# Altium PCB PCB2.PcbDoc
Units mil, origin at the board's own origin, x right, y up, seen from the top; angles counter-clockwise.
Board outline 4495.6 x 2805.51 mil, 2 copper layers (Top Layer, Bottom Layer), stack 61.756 mil thick; 146 components, 111 nets, 456 pads, 126 vias.
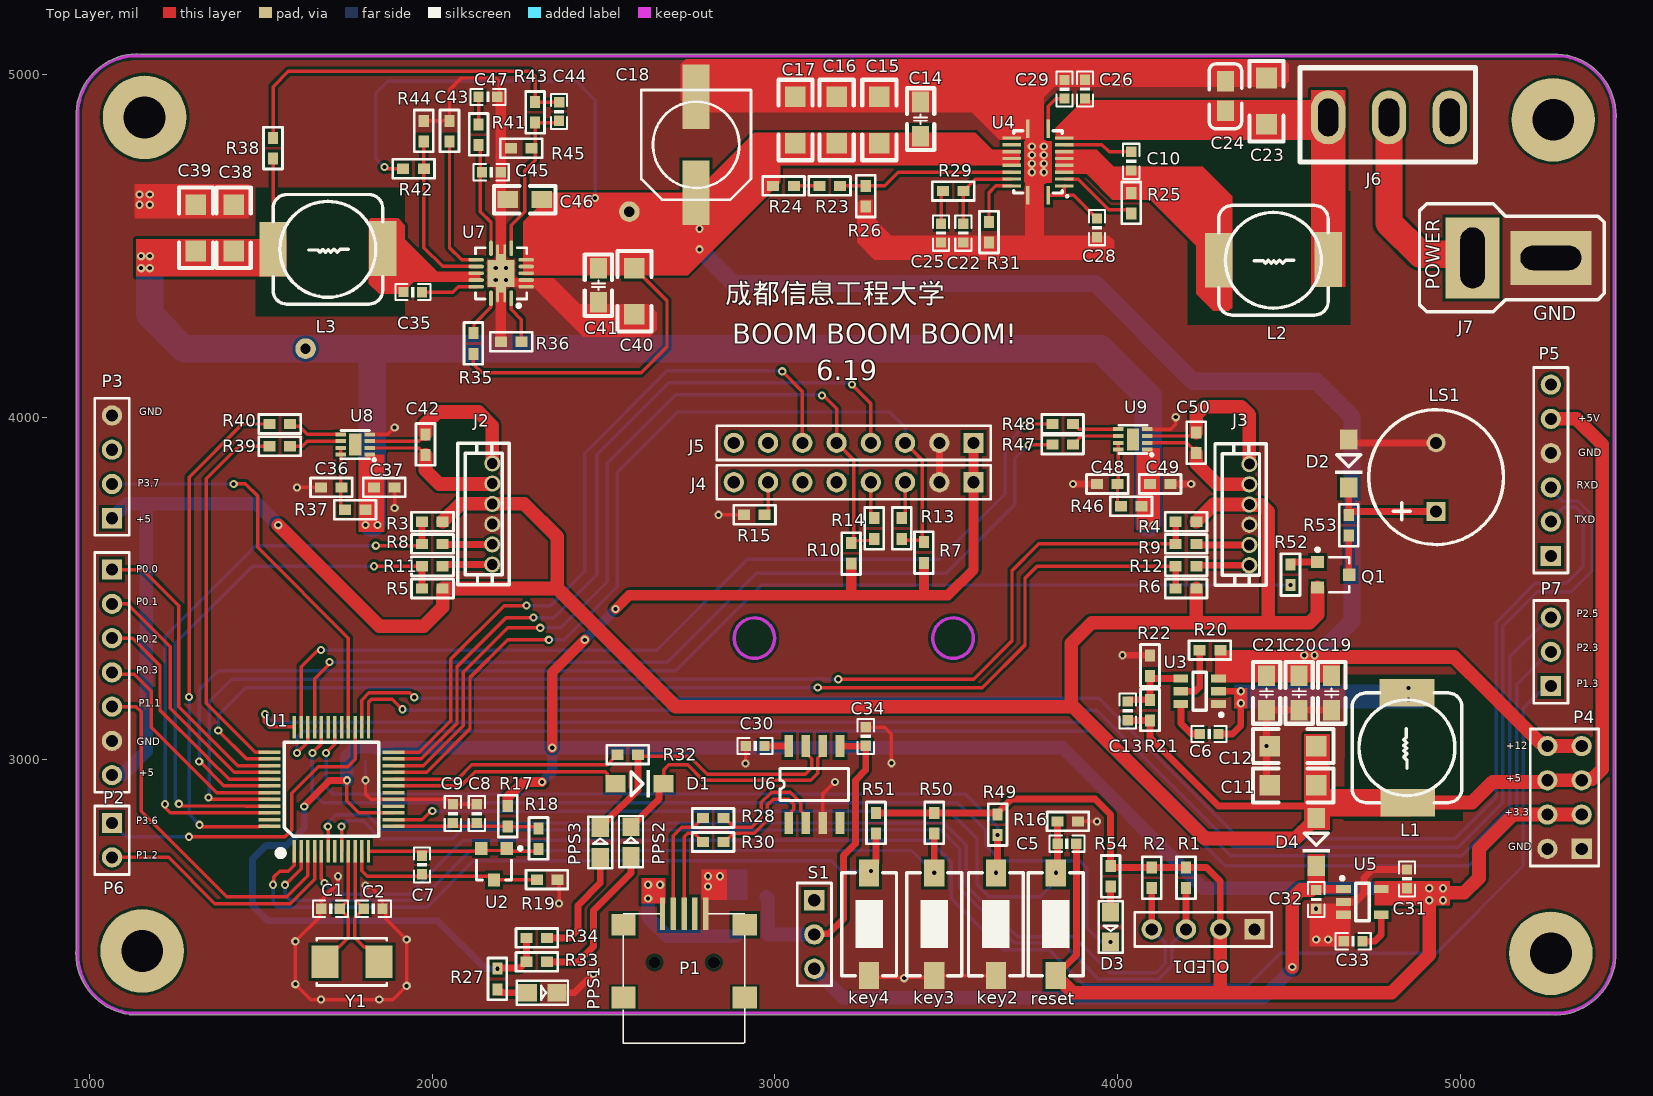
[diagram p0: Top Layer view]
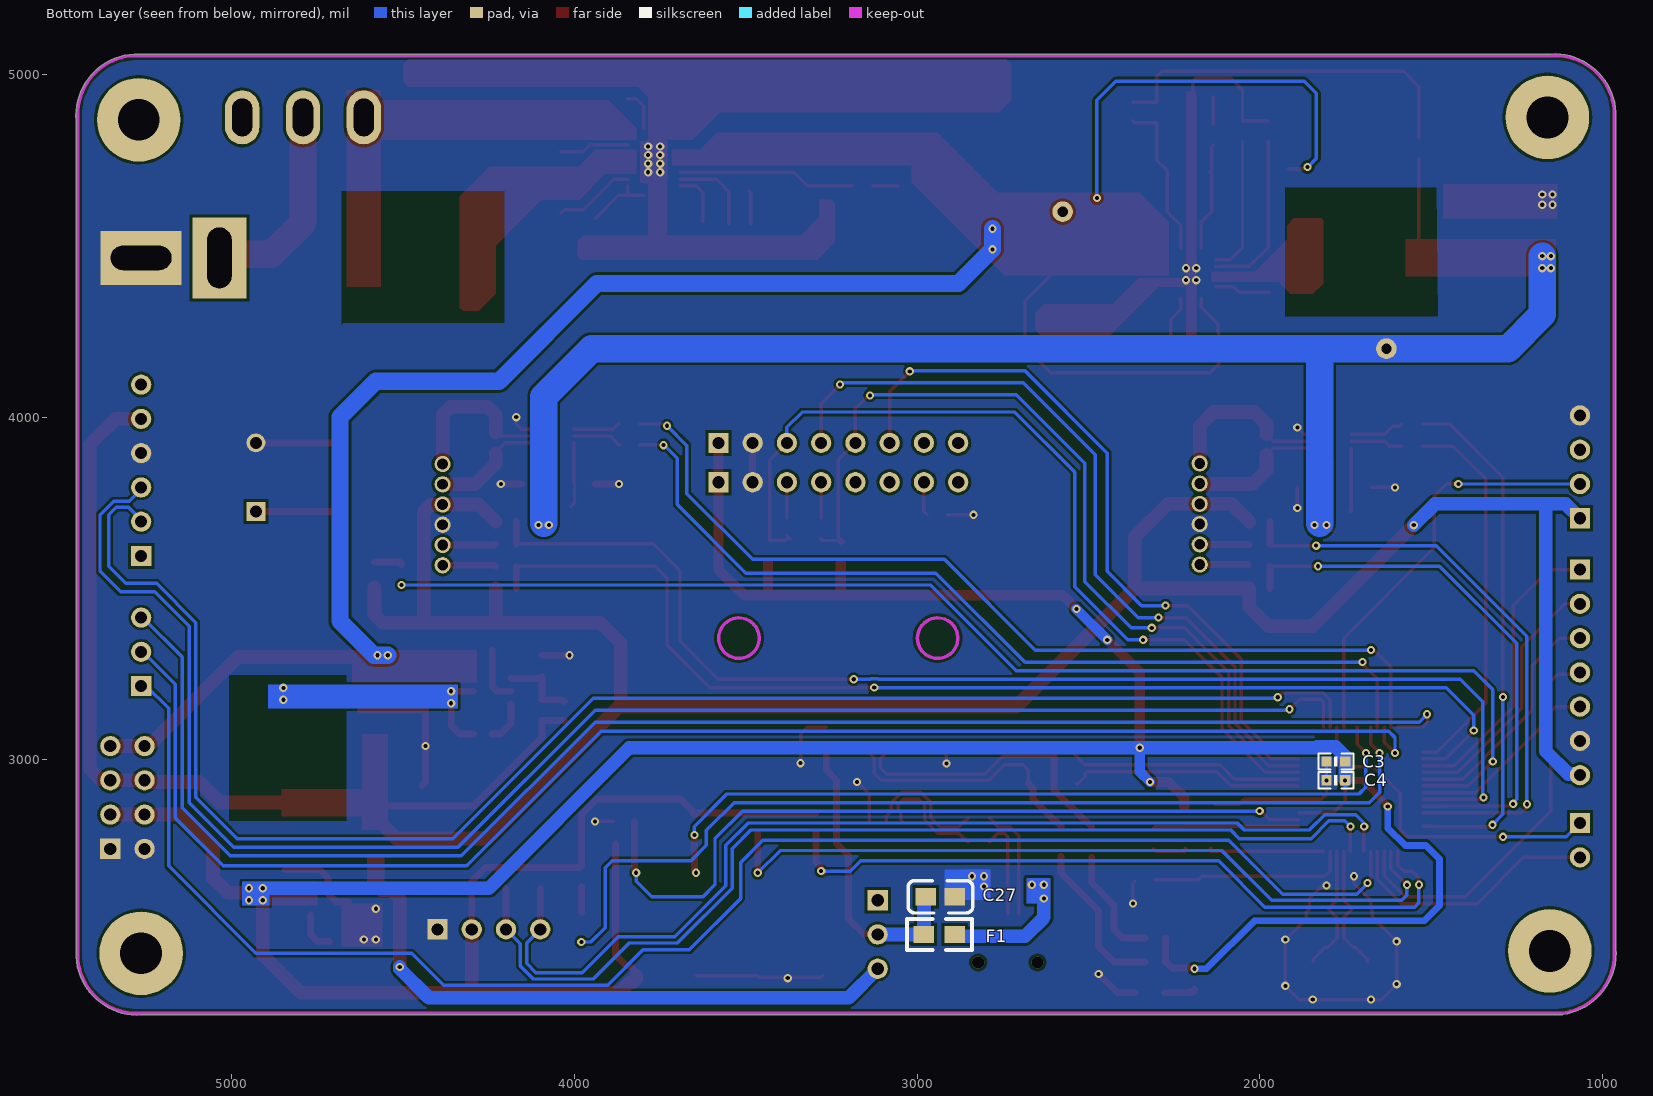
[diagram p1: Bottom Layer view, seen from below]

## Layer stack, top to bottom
Top Solder: solder mask 1, SM-001, Dk 4
Top Layer: signal copper 1.378
Dielectric 1: core 59, Core-043, Dk 4.3
Bottom Layer: signal copper 1.378
Bottom Solder: solder mask 1, SM-001, Dk 4

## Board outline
960.53,2417.73 cw(c965,2420) 959.98,2420 959.98,2424.87 cw(c1140,2435) 959.98,2445.13 959.98,4890 cw(c965,4890) 960,4890.38 cw(c1140,4880) 1150.14,5060.02 5282.5,5060.02 cw(c5282.5,5055) 5283.75,5059.86 cw(c5285,5055) 5285.29,5060.01 cw(c5275,4880) 5455.3,4880 cw(c5275,4880) 5455.02,4869.86 5455.02,2425 cw(c5450,2425) 5455.01,2424.68 ccw(c5275,2435) 5455.01,2424.71 5455.01,2424.68 cw(c5275,2435) 5264.86,2254.99 1130,2254.98 cw(c1130,2260) 1129.66,2255 ccw(c1140,2435) 1129.71,2254.99 1129.66,2255 cw(c1140,2435)

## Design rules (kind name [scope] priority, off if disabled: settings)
Clearance [All] p1: gap=8 ignorepadtopadclearanceinfootprint=FALSE
PolygonConnect [All] p1: connectstyle=Direct reliefconductorwidth=10 reliefentries=4 polygonreliefangle="90 Angle" airgapwidth=10
RoutingVias [All] p1: holewidth=28 width=50 viastyle="Through Hole" minholewidth=28 minwidth=50 maxholewidth=28 maxwidth=50
SolderMaskExpansion [All] p1: expansion=4 istentingtop=FALSE
Width [All] p1: maxlimit=100 minlimit=10 preferedwidth=10 minimp=50.000000 maximp=50.000000 favimp=50.000000
30 further rules are at their usual default settings.

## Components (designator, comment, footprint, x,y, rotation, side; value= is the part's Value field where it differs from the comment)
C1 "22PF" 0603-C 1730,2565 r180 top
C2 "22PF" 0603-C 1800,2565 r0 top
C3 "" 0603-C 1805,2940 r180 bottom value=10UF
C4 "" 0603-C 1805,2995 r180 bottom value=104
C5 "104" 0603-C 3825.5,2755.06 r0 top
C6 "" 0603-c 4295,3075 r180 top value=0.1UF
C7 "100nf" 0603-C 1970,2720 r270 top
C8 "10UF" 0603-C 2129.94,2815.5 r90 top
C9 "100NF" 0603-C 2059.94,2815.5 r90 top
C10 "" 0603-c 4040.06,4774.5 r270 top value=0.1uf
C11 "" 1206 4445,2925 r0 top value=22UF
C12 "" 1206 4445,3040 r0 top value=22UF
C13 "" 0603-c 4030,3170 r270 top value=6.8UF
C14 "" 0805C 3425,4920 r270 top value=1UF
C15 "" 1206 3305,4935 r270 top value=22UF
C16 "" 1206 3180,4935 r270 top value=22UF
C17 "" 1206 3060,4935 r270 top value=22UF
C18 "" CC88 2770,4795 r90 top value=220uf电解
C19 "" 0805c 4625,3245 r270 top value=10UF
C20 "" 0805c 4530,3245 r270 top value=10UF
C21 "" 0805c 4435,3245 r270 top value=0.1UF
C22 "" 0603-C 3550.06,4564.5 r270 top value=100PF
C23 "" 1206 4435,4855 r90 top value=47uf坦
C24 "" 0805-c 4315,4980 r270 top value=10uf
C25 "" 0603-C 3485.06,4564.5 r270 top value=6.8UF
C26 "" 0603-c 3905,4985 r270 top value=0.1uf
C27 "坦47uf" 0805-C 2975,2600 r180 bottom
C28 "" 0603-c 3939.94,4525.5 r90 top value=2.2uf
C29 "" 0603-C 3845,4930 r90 top value=47nf
C30 "0.1uf" 0603-C 2969.5,3039.94 r180 top
C31 "" 0603-C 4845.06,2679.5 r270 top value=1uf
C32 "" 0603-C 4580,2565 r90 top value=1uf
C33 "" 0603-C 4660.5,2470.06 r0 top value=0.1uf
C34 "0.1uf" 0603-C 3265,3095 r270 top
C35 "" 0603-c 1915.5,4365.06 r0 top value=0.1uf
C36 "0.1UF" 0603-r 1735,3795 r180 top
C37 "0.1UF" 0603-r 1830,3795 r0 top
C38 "" 1206 1420,4620 r270 top value=47uf
C39 "" 1206 1310,4620 r270 top value=47uf
C40 "" 1206 2590,4435 r270 top value=22uf坦
C41 "" 0805c 2485,4335 r90 top value=4.7uf
C42 "104" 0603-r 1980,3950 r270 top
C43 "" 0603-r 2050,4865 r270 top value=0.022uf
C44 "" 0603-c 2370,4865 r90 top value=470pf
C45 "" 0603-c 2199.5,4714.94 r180 top value=39pf
C46 "" 0805r 2220,4635 r0 top value=4.7uf
C47 "" 0603-c 2189.5,4934.94 r180 top value=3900pf
C48 "0.1UF" 0603-r 4000,3805 r180 top
C49 "0.1UF" 0603-r 4095,3805 r0 top
C50 "104" 0603-r 4230,3955 r270 top
D1 "二极管" DIODE_SOP 2535,2930 r0 top
D2 "DIODE" "DIODE_SOP - duplicate1" 4675,3935 r270 top
D3 "LED0" 0805-LED 3980,2507.36 r270 top
D4 "DIODE" "DIODE_SOP - duplicate1" 4580,2830 r270 top
F1 "500mA保险丝" "0805 - duplicate" 2890,2490 r0 bottom
J2 "CON6" XH6-1.5x1.5 2175,3865 r270 top
J3 "CON6" XH6-1.5x1.5 4385,3863.1 r270 top
J4 "CON8" HDR1X8 3580,3810 r180 top
J5 "CON8" HDR1X8 3580,3925 r180 top
J6 "主开关" 拨动开关 4790,4880 r90 top
J7 "T插" T型头 5138,4473 r0 top
key2 "KEY" KEY 3645,2520 r270 top
key3 "KEY" KEY 3465,2520 r270 top
key4 "KEY" KEY 3275,2520 r270 top
L1 "Inductor" L8*8 4845,2875 r90 top value=4.7uh
L2 "PIMB   0630" L8*8 4615,4458 r180 top value=2.2uh
L3 "Inductor" L8*8 1855,4490 r180 top value=3.3uh
LS1 "SPEAK" BELL-5 4930,3725 r90 top
OLED1 "CON4" HDR1X4 4400,2505 r180 top
P1 "USB_Micro" "USB_MINI - duplicate" 2735,2172.05 r90 top
P2 "Header 7" HDR1X7 1065,3555 r270 top
P3 "Header 4" HDR1X4 1065,3705 r90 top
P4 "Header 4X2" HDR2X4 5355,2740 r90 top
P5 "Header 6" HDR1X6 5265,3595 r90 top
P6 "Header 2H" HDR1X2 1065,2815 r270 top
P7 "Header 3" HDR1X3 5265,3215 r90 top
PPS1 "LED" 0805-LED 2325,2320 r0 top
PPS2 "LED" 0805-LED 2580,2765 r90 top
PPS3 "LED" 0805-LED 2490,2762.64 r90 top
Q1 "PNP" SOT-23R 4625,3540 r270 top
R1 "" 0603-R 4200,2685 r270 top value=4.7K
R2 "" 0603-R 4100,2685 r270 top value=4.7K
R3 "10K" 0603-R 2030,3695 r180 top
R4 "10K" 0603-R 4230,3695 r180 top
R5 "10K" 0603-R 2030,3500 r180 top
R6 "10K" 0603-R 4230,3500 r180 top
R7 "" 0603-R 3435,3575 r90 top value=4.7K
R8 "510R" 0603-R 2030,3630 r180 top
R9 "510R" 0603-R 4230,3630 r180 top
R10 "" 0603-R 3222.5,3572.5 r90 top value=4.7K
R11 "510R" 0603-R 2030,3565 r180 top
R12 "510R" 0603-R 4230,3565 r180 top
R13 "200R" 0603-R 3370,3705 r270 top
R14 "200R" 0603-R 3290,3705 r270 top
R15 "4.7k" 0603-R 2970,3715 r180 top
R16 "10k" 0603-R 3885,2820 r180 top
R17 "Res1" 0603-R 2220,2865 r270 top value=0R
R18 "Res1" 0603-R 2310,2800 r270 top value=511R
R19 "Res1" 0603-R 2305,2650 r0 top value=0R
R20 "" 0603-r 4240,3320 r0 top value=10K
R21 "" 0603-r 4095,3175 r270 top value=54.9K
R22 "" 0603-r 4095,3305 r270 top value=10K
R23 "Res1" 0603-R 3130,4675 r0 top value=504K
R24 "Res1" 0603-R 3055,4675 r180 top value=100Ω微
R25 "" 0603-r 4040,4655 r270 top value=255k
R26 "Res1" 0603-R 3265,4675 r270 top value=56K
R27 "1K" 0603-R 2190,2390 r270 top
R28 "22R" 0603-R 2790,2830 r0 top
R29 "" 0603-R 3550,4660 r180 top value=121k
R30 "22R" 0603-R 2790,2760 r0 top
R31 "Res1" 0603-R 3625,4570 r270 top value=100K
R32 "300R" 0603-R 2600,3015 r180 top
R33 "1K" 0603-R 2335,2410 r180 top
R34 "1K" 0603-R 2335,2480 r180 top
R35 "" 0603-r 2120,4245 r270 top value=49.9K
R36 "" 0603-r 2260,4220 r180 top value=100K
R37 "1K" 0603-r 1745,3730 r0 top
R38 "" 0603-r 1535,4815 r270 top value=0R
R39 "200Ω" 0603-r 1525,3915 r0 top
R40 "200Ω" 0603-r 1525,3980 r0 top
R41 "Res1" 0603-r 2135,4855 r270 top value=4.64K
R42 "" 0603-r 1975,4725 r180 top value=35.7K
R43 "" 0603-r 2300,4860 r90 top value=19.89K
R44 "" 0603-r 1975,4865 r270 top value=8.06K
R45 "" 0603-r 2230,4785 r0 top value=2.21K
R46 "1K" 0603-r 4010,3740 r0 top
R47 "200Ω" 0603-r 3810,3920 r0 top
R48 "200Ω" 0603-r 3810,3980 r0 top
R49 "10K" 0603-R 3650,2840 r270 top
R50 "10k" 0603-R 3465,2845 r270 top
R51 "10k" 0603-R 3295,2845 r270 top
R52 "1k" 0603-R 4505,3570 r270 top value=1K
R53 "100R" 0603-R 4675,3655 r90 top
R54 "Res1" 0603-R 3980,2630 r90 top value=1K
reset "KEY" KEY 3820,2520 r270 top (schematic designator key1)
S1 "switch" HDR1X3 3115,2590 r270 top
U1 "STC8A8K64S4A12-48" LQFP48S 1597.5,2732.37 r90 top
U2 "TL431" SOT-23 2180,2700 r180 top
U3 "TPS562201" LC-SOT-23-6 4240,3200 r0 top
U4 "TPS61008" TPS61088改 3768,4744.92 r90 top
U5 "TPS79133" LC-SOT-23-5 4715,2585 r180 top
U6 "CH340N" SOP-8 3040,2815.59 r90 top
U7 "TPS54821" VQFN-14改 2200.83,4420 r90 top
U8 "drv8837" wson-8-2X2改 1775,3920 r180 top
U9 "drv8837" wson-8-2X2改 4045,3935 r180 top
Y1 "XTAL_5032" XTAL_5032 1765,2410 r180 top value=4M~33M

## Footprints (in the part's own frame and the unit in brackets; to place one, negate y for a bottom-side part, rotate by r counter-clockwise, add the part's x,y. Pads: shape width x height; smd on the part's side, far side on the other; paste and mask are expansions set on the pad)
0603-C [mil]
  rect 30x30 smd: 1(0,0) 2(54.5,-0.06)
  silkscreen extent -24,-24 79,24
0603-c [mil]
  rect 30x30 smd: 1(0,0) 2(54.5,-0.06)
  silkscreen extent -24,-24 79,24
0603-r [mil]
  rect 35x30 smd: 1(0,0) 2(60,0)
  silkscreen extent -31,-28 91,28, body extent -22,-19 82,19, height 39
0603-R [mil]
  rect 35x30 smd: 1(0,0) 2(60,0)
  silkscreen extent -31,-28 91,28, body extent -22,-19 82,19, height 39
"0805 - duplicate" [mil]
  rect 60x50 smd: 1(0,0) 2(90,0)
  silkscreen extent -50,-45 140,45
0805-c [mil]
  rect 60x50 smd: 1(0,0) 2(85,0)
  silkscreen extent -51,-47 138,47, body extent 3,-25 82,25, height 30
0805-C [mil]
  rect 60x50 smd: 1(0,0) 2(85,0)
  silkscreen extent -51,-47 138,47, body extent 3,-25 82,25, height 30
0805-LED [mm]
  rect 1.4x1.27 smd: 1(-1.21,0) 2(1,0)
  silkscreen extent -2.01,-0.89 1.8,0.89
0805C [mil]
  rect 60x49.21 smd: 1(0,0) 2(100,0)
  silkscreen extent -40,-40 140,40
0805c [mil]
  rect 60x49.21 smd: 1(0,0) 2(100,0)
  silkscreen extent -40,-40 140,40
0805r [mil]
  rect 60x49.21 smd: 1(0,0) 2(100,0)
  silkscreen extent -40,-40 140,40
1206 [mil]
  rect 60x60 smd: 1(0,0) 2(135,0)
  silkscreen extent -50,-50 185,50
BELL-5 [mil] "PIN:5MM,SIZE:10MM"
  rect 55x55 hole 35: 1(0,0)
  round 55 hole 35: 2(200,0)
  silkscreen extent -97,-197 297,197
CC88 [mm] "SMD;W:8mm;L:8mm;"
  rect 4.8x2 smd: 1(-3.556,0) 2(3.556,0)
  silkscreen extent -4.06,-4.06 4.06,4.06
DIODE_SOP [mm]
  rect 1.5x1.3 smd: 1(0,0) 2(3.556,0)
  silkscreen extent 1.14,-1.02 2.56,1.02
"DIODE_SOP - duplicate1" [mm]
  rect 1.5x1.3 smd: 1(0,0) 2(3.556,0)
  silkscreen extent 1.14,-1.02 2.56,1.02
HDR1X2 [mm] "Connector; Header; 2 Position"
  rect 1.5x1.5 hole 0.9: 1(0,0)
  round 1.5 hole 0.9: 2(2.54,0)
  silkscreen extent -1.27,-1.27 3.81,1.27
HDR1X3 [mm] "Connector; Header; 3 Position"
  rect 1.5x1.5 hole 0.9: 1(0,0)
  round 1.5 hole 0.9: 2(2.54,0) 3(5.08,0)
  silkscreen extent -1.27,-1.27 6.35,1.27
HDR1X4 [mm] "Connector; Header; 4 Position"
  rect 1.5x1.5 hole 0.9: 1(0,0)
  round 1.5 hole 0.9: 2(2.54,0) 3(5.08,0) 4(7.62,0)
  silkscreen extent -1.27,-1.27 8.89,1.27
HDR1X6 [mm] "Connector; Header; 6 Position"
  rect 1.5x1.5 hole 0.9: 1(0,0)
  round 1.5 hole 0.9: 2(2.54,0) 3(5.08,0) 4(7.62,0) 5(10.16,0) 6(12.7,0)
  silkscreen extent -1.27,-1.27 13.97,1.27
HDR1X7 [mm] "Connector; Header; 7 Position"
  rect 1.5x1.5 hole 0.9: 1(0,0)
  round 1.5 hole 0.9: 2(2.54,0) 3(5.08,0) 4(7.62,0) 5(10.16,0) 6(12.7,0) 7(15.24,0)
  silkscreen extent -1.27,-1.27 16.51,1.27
HDR1X8 [mm] "Connector; Header; 8 Position"
  rect 1.5x1.5 hole 0.9: 1(0,0)
  round 1.5 hole 0.9: 2(2.54,0) 3(5.08,0) 4(7.62,0) 5(10.16,0) 6(12.7,0) 7(15.24,0) 8(17.78,0)
  silkscreen extent -1.27,-1.27 19.05,1.27
HDR2X4 [mm] "Connector; Header; 4x2 Position"
  rect 1.5x1.5 hole 0.9: 1(0,0)
  round 1.5 hole 0.9: 2(0,2.54) 3(2.54,0) 4(2.54,2.54) 5(5.08,0) 6(5.08,2.54) 7(7.62,0) 8(7.62,2.54)
  silkscreen extent -1.27,-1.27 8.89,3.81
KEY [mm]
  rect 2x1.5 smd: 1(-3.81,0) 2(3.81,0)
  silkscreen extent -3.81,-2.03 3.81,2.03
L8*8 [mil]
  rect 80x160 smd: 1(0,-2) 2(320,0)
  silkscreen extent 0,-160 320,160
LC-SOT-23-5 [mm]
  rect 1.1x0.6 smd: 1(1.4,-0.95) 2(1.4,0) 3(1.4,0.95) 4(-1.4,0.95) 5(-1.4,-0.95)
  silkscreen extent -0.5,-1.87 1.62,1.4
LC-SOT-23-6 [mm]
  rect 1.1x0.6 smd: 1(1.4,-0.95) 2(1.4,0) 3(1.4,0.95) 4(-1.4,0.95) 5(-1.4,0) 6(-1.4,-0.95)
  silkscreen extent -0.5,-1.87 1.73,1.4
LQFP48S [mil] "DPIN-0.5"
  rect 65x10 smd: 1(0.42,0.29) 2(0.42,-19.39) 3(0.42,-39.08) 4(0.42,-58.76) 5(0.42,-78.45) 6(0.42,-98.13) 7(0.42,-117.82) 8(0.42,-137.5) 9(0.42,-157.19) 10(0.42,-176.87) 11(0.42,-196.56) 12(0.42,-216.24) 25(362.63,-216.24) 26(362.63,-196.56) 27(362.63,-176.87) 28(362.63,-157.19) 29(362.63,-137.5) 30(362.63,-117.82) 31(362.63,-98.13) 32(362.63,-78.45) 33(362.63,-58.76) 34(362.63,-39.08) 35(362.63,-19.39) 36(362.63,0.29)
  rect 10x65 smd: 13(73.26,-289.08) 14(92.94,-289.08) 15(112.63,-289.08) 16(132.31,-289.08) 17(152,-289.08) 18(171.68,-289.08) 19(191.37,-289.08) 20(211.05,-289.08) 21(230.74,-289.08) 22(250.42,-289.08) 23(270.11,-289.08) 24(289.79,-289.08) 37(289.79,73.13) 38(270.11,73.13) 39(250.42,73.13) 40(230.74,73.13) 41(211.05,73.13) 42(191.37,73.13) 43(171.68,73.13) 44(152,73.13) 45(132.31,73.13) 46(112.63,73.13) 47(92.94,73.13) 48(73.26,73.13)
  silkscreen extent -10,-246 319,46
SOP-8 [mil]
  rect 65x25 smd: 1(0,0) 2(0,-50) 3(0,-100) 4(0,-150) 5(224.41,-150) 6(224.41,-100) 7(224.41,-50) 8(224.41,0)
  silkscreen extent 65,-175 159,25
SOT-23 [mm] "SOT-23; 3 Leads; Body 3.0 x 2.5 mm, inc. leads (LxW max)"
  rect 0.9x0.95 smd: 1(-0.95,-1.048) 2(0.95,-1.048) 3(0,1.302)
  silkscreen extent -2.07,-1.17 1.3,1.3
SOT-23R [mm]
  rect 0.9x0.95 smd: 1(0.95,-1.048) 2(-0.95,-1.048) 3(0,1.302)
  silkscreen extent -1.98,-1.17 1.3,1.3
TPS61088改 [mil]
  rect 54x9.6 smd: 1(-97,-30.02) 10(97,-30.02) 11(97,29.98) 20(-97,29.98)
  rect 9.6x54 smd: 2(-69.92,-77) 3(-49.92,-77) 4(-29.92,-77) 5(-9.92,-77) 6(10.08,-77) 7(30.08,-77) 8(50.48,-77) 9(70.08,-77) 12(70.08,76.9) 13(50.08,76.9) 14(30.08,76.9) 15(10.08,76.9) 16(-9.92,76.9) 17(-29.92,76.9) 18(-49.92,76.9) 19(-69.92,76.9)
  Top Layer region: -63.74,5.69 -105,5.74 -105,14.75 -63.82,14.94 -63.7,22.22 -59.92,22.26 -59.88,39.98 60.08,39.98 59.96,22.46 63.82,22.46 63.94,14.98 105,14.98 105,5.77 63.82,5.77 63.94,-5.41 105,-5.41 105,-14.63 63.82,-14.63 63.94,-22.11 60.08,-22.11 60.08,-39.94 -59.92,-40.02 -59.92,-22.34 -63.78,-22.34 -63.74,-14.74 -105.09,-14.74 -105.05,-5.64 -63.7,-5.69
  silkscreen extent -104,-89 91,71
T型头 [mm]
  rect 4x6 hole 1.8 slot 4.5 at 90 deg: 1(-2.574,-0.203)
  rect 6x4 hole 1.8 slot 4.5 at 0 deg: 2(3.226,-0.203)
  silkscreen extent -6.51,-4.2 7.19,3.8
"USB_MINI - duplicate" [mm]
  rect 1.6x1.8 smd: 0(3.4,-4.5) 0(3.4,4.5) 0(8.8,-4.5) 0(8.8,4.5)
  rect 2.4x0.4 smd: 1(9.6,1.6) 2(9.6,0.8) 3(9.6,0) 4(9.6,-0.8) 5(9.6,-1.6)
  silkscreen extent 0,-4.5 9.6,4.5
VQFN-14改 [mm]
  oval 1.155x0.28 smd mask+0.051: 1(-1.854,-0.75) 7(1.854,-0.753) 8(1.854,0.75) 14(-1.854,0.75)
  oval 0.28x1.155 smd mask+0.051: 2(-1,-1.854) 3(-0.5,-1.854) 4(0,-1.854) 5(0.5,-1.854) 6(1,-1.854) 9(1,1.854) 10(0.5,1.854) 11(0,1.854) 12(-0.5,1.854) 13(-1,1.854)
  oval 4.3x0.2 smd mask+0.051: 15(0,0.275) 15(0,-0.275)
  rect 2.85x0.35 smd: 15(0,0)
  rect 2x2 smd: 15(0,0)
  silkscreen extent -2.52,-1.9 1.9,1.9
wson-8-2X2改 [mil]
  rect 30.5x11.5 smd: 1(-42.4,29) 2(-42.4,10) 3(-42.4,-10) 4(-42.4,-30) 5(42.4,-30) 6(42.4,-10) 7(42.4,10) 8(42.4,29)
  rect 35.5x63.5 smd: 9(0,0)
  silkscreen extent -58,-41 41,47
XH6-1.5x1.5 [mm]
  round 1.2 hole 0.8: 1(0,0) 2(1.499,0) 3(3,0) 4(4.498,0) 5(5.999,-0.003) 6(7.503,-0.003)
  silkscreen extent -1.5,-2.55 9,1.25
XTAL_5032 [mm]
  rect 2x2.4 smd: 1(-2,0) 2(2,0)
  silkscreen extent -2.6,-1.75 2.6,1.75, body extent -2.5,-1.6 2.5,1.6, height 1
拨动开关 [mm]
  oval 4x2.54 hole 1.5 slot 2.8 at 0 deg: 1(-0.127,-0.064) 2(-0.127,4.445) 3(-0.127,-4.572)
  silkscreen extent -3.44,-6.48 3.56,6.52

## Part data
C1 C2 C5 C36 C37 C42 C48 C49 C50: library part CAP_0805
C3 C4 C6 C10 C11 C12 C13 C14 C15 C16 C17 C19 C20 C21 C22 C24 C25 C26 C28 C29 C31 C32 C33 C35 C38 C39 C41 C43 C44 C45 C46 C47: library part Cap, "Capacitor"
C7 C8 C9 C27 C30 C34: library part CAP
C18 C23 C40: library part "Cap Pol1", "Polarized Capacitor (Radial)"
D1: library part D_1, "1N4148"
D2 D4: library part Diode_1_2, "Default Diode"
D3: "Typical INFRARED GaAs LED"
F1: library part "Fuse 2", "Fuse"
J6: library part CON3
J7: library part CON2
L2: library part Inductor, "Inductor"
LS1: "Electrical Bell"
P1: "USB"
P2: "Header, 7-Pin"
P3: "Header, 4-Pin"
P4: "Header, 4-Pin, Dual row"
P5: "Header, 6-Pin"
P6: "Header, 2-Pin, Right Angle"
P7: "Header, 3-Pin"
Q1: library part PNP_5, "8550/BCW68"
R1 R2 R7 R10 R20 R21 R22 R25 R29 R35 R36 R38 R42 R43 R44 R45: library part Res1, "Resistor"
R3 R4 R5 R6 R8 R9 R11 R12 R13 R14 R15 R16 R27 R28 R30 R32 R33 R34 R37 R39 R40 R46 R47 R48 R49 R50 R51: library part RES, "Resistor"
R17 R18 R19 R23 R24 R26 R31 R41 R54: "Resistor"
R52 R53: library part Res_0603, "Resistor"
S1: library part "SW DPDT", "Switch"
U8 U9: library part DRV8837DSGR
Y1: "Crystal Oscillator"

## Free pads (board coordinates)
  round 60 hole 30: 3(2575,4600) 4(1630,4200)
  round 244.09 hole 122.05: ""(1153,2442) ""(1160,4875) ""(5265,2435) ""(5272,4868)

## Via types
v1: diameter 24, hole 12, Top Layer to Bottom Layer, 124 vias
v2: diameter 35.43, hole 35.43, Top Layer to Bottom Layer, 2 vias

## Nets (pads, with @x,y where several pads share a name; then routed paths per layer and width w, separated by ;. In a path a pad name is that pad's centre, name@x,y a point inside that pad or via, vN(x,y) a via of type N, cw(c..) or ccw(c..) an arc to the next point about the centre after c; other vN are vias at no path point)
5V-VCC: C32.2 D4.2 S1.3 U5.1 | length 1742.4
  Top Layer w40: v1(4510,2395) 4510,2594.85 4534.75,2619.6 4564.6,2619.6 C32.2@4569.78,2624.78
  Bottom Layer w40: S1.3 3200,2305 4425,2305 4510,2390 v1(4510,2395)
12V-VCC: C14.2 C15.2 C16.2 C17.2 C18.1 C19.1 C20.1 C21.1 C40.1 C41.2 C46.2 P4.7 P4.8 pad.3 R20.2 R24.2 R35.2 R42.2 U3.3 U4.14 U4.15 U4.16 U7.4 U7.5 U7.6 | length 5983.7
  Top Layer w10: v1(1860,4730) 1863.79,4730 1868.79,4725 R42.2 ; R35.2 2120,4155 2145,4130 2610,4130 2685,4205 2685,4340 2615,4410 C40.1 ; 2475,4615 2470,4620 2475,4625 v1(2475,4640)
  Top Layer w40: 4600,3300 4982.55,3300 5085,3197.55 5233.02,3049.53 5240.32,3049.53 5246.2,3043.65 P4.8@5246.2,3036.35 ; P4.8 P4.7
  Bottom Layer w10: v1(1860,4730) 1835,4755 1835,4945 1870,4980 2420,4980 2475,4925 v1(2475,4640)
  Bottom Layer w50: v1(2780,4550) v1(2780,4490) 2880,4390 3935,4390 4220,4105 4580,4105 4685,4000 4685,3405 4585,3305 v1(4545,3305)
  other v1: 4575,3305
AD0: J4.7 R15.1 | length 99.1
  Top Layer w10: R15.1 2980,3725 J4.7
AGND: C7.2 R19.1 U1.11 U2.3 | length 579.6
  Top Layer w10: U1.11 1794.06,2675.94 1810,2660 1969.94,2660 2168.74,2660 U2.3 2181.26,2650 R19.1
AVCC: C8.1 C9.1 R17.2 R18.1 U1.13 | length 425.8
  Top Layer w10: U1.13 2059.94,2805.63 2129.94,2805.63 2219.37,2805.63 R17.2 2305,2805 R18.1
BOOST_IN: C23.1 C24.2 C26.2 J6.2 L2.1 U4.9
CS: J5.6 U1.24 | length 2136.5
  Top Layer w10: U1.24 1961.71,3022.17 2054,3114.46 2054,3294 2210,3450 v1(2275,3450) ; v1(3021.25,4133.75) 3080,4075 J5.6
  Bottom Layer w10: v1(2275,3450) 2345,3450 2445,3550 2445,3895 2685,4135 3020,4135 v1(3021.25,4133.75)
DRV-6V: C37.1 C38.2 C39.2 C49.1 L3.2 pad.4 R37.2 R38.2 R46.2 U8.1 U9.1 | length 4329.4
  Top Layer w10: L3.2 R38.2
  Bottom Layer w80: v1(1175,4470) v1(1175,4435) 1175,4300 1275,4200 1825,4200 ; 1825,3690 1825,4200 ; 4090,3690 4090,4060 3950,4200 1825,4200
  other v1: 1805,3685 1840,3685 4075,3685 4105,3685 1150,4435 1150,4470
EN: R42.1 R44.2 U7.10 | length 485.7
  Top Layer w10: R44.2 R42.1 1975,4495 2030,4440 2109.57,4440 2109.69,4439.88 2127.63,4439.88 U7.10
FSY: J5.8
GND: C1.2 C2.2 C3.1 C4.1 C8.2 C9.2 C11.1 C12.1 C14.1 C15.1 C16.1 C17.1 C18.2 C19.2 C20.2 C21.2 C22.2 C23.2 C24.1 C25.2 C26.1 C27.2 C28.1 C29.2 C30.2 C31.1 C32.1 C33.1 C34.1 C36.2 C37.2 C38.1 C39.1 C40.2 C41.1 C43.1 C45.1 C46.1 C47.1 C48.2 C49.2 D2.1 J2.4 J3.4 J4.2 J5.2 J7.2 key2.2 key3.2 key4.2 LS1.2 OLED1.1 P1.5 P2.6 P3.4 P4.1 P4.2 P5.4 PPS1.2 R15.2 R16.1 R19.2 R22.1 R26.2 R31.2 R36.2 R44.1 R45.1 U1.17 U3.1 U4.11 U4.12 U4.20 U5.2 U5.3 U6.3 U7.2 U7.3 U7.15 U8.4 U9.4 | length 4484
  Top Layer w10: v1(1605,3795) C36.2 ; v1(1725,2660) 1725,2640 1675.5,2590.5 C1.2 1670.92,2560.49 1670.92,2540.92 v1(1600,2470) v1(1600,2345) 1645,2300 v1(1675,2300) v1(1845,2300) 1885,2300 v1(1925,2340) v1(1925,2475) 1864.5,2535.5 1864.5,2554.94 C2.2 1854.5,2595.5 1821.59,2628.41 1809.59,2628.41 v1(1805,2633) ; v1(1805,2940) 1805,2900 1820.63,2884.37 U1.17 2045.63,2884.37 C9.2 C8.2 ; U8.4 1870,3950 v1(1890,3970) ; v1(1890,3735) C37.2 ; R44.1 C43.1 2050,4955 2085,4990 2185,4990 2195,4980 2195,4950 ; R19.2@2365,2645 2370,2640 v1(2370,2580) ; v1(2835,3715) R15.2 ; v1(2914.39,2989.39) 2910,2993.79 2915,2998.79 C30.2 ; U6.3 3140,2900 v1(3175,2935) ; C34.1 3320,3095 3340,3075 v1(3340,2990) ; key4.2 3280,2365 v1@3377.5,2365 ; v1(3377.5,2362.5) 3380,2365 3460,2365 key3.2 key2.2 ; R16.1 v1(3940,2820) ; U9.4 4155,3965 4170,3980 v1(4170,4000)
  Top Layer w20: PPS1.2 2415,2320 v1(2470,2375) ; J4.2 J5.2 ; v1(3870,3805) C48.2 ; v1@4025,3305 R22.1 ; C49.2 v1(4215,3805) ; C11.1 4435,2935 C21.2 C20.2 C19.2 ; U5.2 4695.31,2585 4720,2609.68 4720,2655 4744.5,2679.5 C31.1 ; D2.1 4685,3925 LS1.2
  Bottom Layer w10: v1(1805,2940) C4.1
  other v1: 4580,2475 4615,2475 4580,2565 2805,2630 2805,2660 2840,2660 4435,3040 4015,3305 2185,4400 2215,4400 2185,4435 2215,4435 1145,4620 1175,4620 1145,4650 1175,4650 3750,4715 3785,4715 3750,4740 3785,4740 3750,4765 3785,4765 3750,4790 3785,4790
INT: J4.8
INT1: J5.7
NetC6_1: C6.1 L1.2 U3.2 | length 240.2
  Top Layer w20: C6.1 4335,3075 4360,3100 v1(4360,3200) U3.2
  other v1: 4360,3165 4850,3175 4850,3210
NetC6_2: C6.2 U3.6 | length 124.8
  Top Layer w20: U3.6 4184.88,3106.38 4216.2,3075.06 C6.2
NetC10_1: C10.1 U4.8 | length 203.7
  Top Layer w10: U4.8 3954.6,4795.4 3975.5,4774.5 C10.1
NetC10_2: C10.2 L2.2 R25.1 U4.4 U4.5 U4.6 U4.7
NetC13_1: C13.1 R21.1 R22.2 U3.4 | length 226.6
  Top Layer w20: C13.1 4035,3175 R21.1 4095,3242.5 4100,3237.5 4111.62,3237.5 4111.72,3237.4 U3.4
NetC22_1: C22.1 R29.1 U4.18 | length 252.6
  Top Layer w10: C22.1 3550,4564.56 R29.1 3552.5,4660 3562.5,4670 3562.5,4672.5 3585,4695 U4.18
NetC25_1: C25.1 R29.2 | length 97.5
  Top Layer w10: C25.1 3485.06,4655.06 R29.2
NetC28_2: C28.2 U4.1 U4.2 | length 192
  Top Layer w10: U4.1 3850.21,4647.92 3872.08,4647.92 C28.2 ; 3845,4653.13 U4.2
NetC29_1: C29.1 U4.10 | length 122.2
  Top Layer w10: U4.10 3798.02,4908.02 3820,4930 C29.1
NetC30_1: C30.1 U6.8 | length 70.5
  Top Layer w20: C30.1 2969.56,3040 U6.8
NetC33_2: C33.2 U5.4 | length 120.9
  Top Layer w20: C33.2 4750,2470 4770,2490 4770,2547.48 U5.4
NetC35_1: C35.1 L3.1 U7.11 U7.12
NetC35_2: C35.2 U7.13 | length 164.3
  Top Layer w10: C35.2 2060,4365 2075.63,4380.63 U7.13
NetC36_1: C36.1 R37.1 U8.7 U8.8 | length 186
  Top Layer w10: U8.7 U8.8 1732.6,3795 1732.6,3727.4 R37.1@1735,3725
NetC43_2: C43.2 U7.9 | length 402.6
  Top Layer w10: C43.2 2050,4495 2085.63,4459.37 U7.9
NetC44_2: C44.2 R38.1 R43.2 | length 1085.1
  Top Layer w10: R38.1 1535,4965 1580,5010 2285,5010 2300,4995 R43.2 2300.5,4919.5 C44.2
NetC45_2: C45.2 R41.2 U7.8 | length 321.2
  Top Layer w10: R41.2 2140,4790 2140,4720 C45.2 2140,4710 2140,4600 2171.3,4568.7 U7.8
NetC47_2: C47.2 R41.1 | length 80
  Top Layer w10: R41.1 C47.2
NetC48_1: C48.1 R46.1 U9.7 U9.8 | length 190.2
  Top Layer w10: U9.7 U9.8 4002.6,3807.6 C48.1 4000,3750 R46.1
NetD2_2: D2.2 LS1.1 R53.2 | length 347.1
  Top Layer w20: R53.2@4670,3725 R53.2@4675,3725 ; R53.2 R53.2@4675,3717.5 ; D2.2 R53.2@4675,3725 ; R53.2@4680,3722.5 R53.2@4675,3717.5 ; LS1.1 R53.2@4675,3725 ; R53.2@4675,3717.5 R53.2@4675,3725
NetD3_1: D3.1 R54.1 | length 75
  Top Layer w20: D3.1 R54.1
NetF1_1: F1.1 P1.1 | length 379.9
  Bottom Layer w40: v1(2630,2635) 2630,2540 2685,2485 2885,2485 F1.1
  other v1: 2630,2595 2665,2635
NetJ2_5: J2.5 R8.1 | length 145.4
  Top Layer w10: R8.1 R8.1@2031.2,3628.8
  Top Layer w20: R8.1@2031.2,3628.8 J2.5
NetJ2_6: J2.6 R11.1 | length 146.8
  Top Layer w10: R11.1 R11.1@2034.6,3569.6
  Top Layer w20: R11.1@2034.6,3569.6 J2.6
NetJ3_5: J3.5 R9.1 | length 156.2
  Top Layer w20: R9.1 4233.1,3626.9 J3.5
NetJ3_6: J3.6 R12.1 | length 156
  Top Layer w20: R12.1 4232.7,3567.7 J3.6
NetJ4_3: J4.3 R13.1 | length 105
  Top Layer w10: R13.1@3380,3705 J4.3
NetJ4_4: J4.4 R14.1 | length 105
  Top Layer w10: R14.1@3280,3705 J4.4
NetP1_2: P1.2 R28.1 | length 337.8
  Top Layer w10: P1.2 2703.5,2778.5 2728,2803 2763,2803 2777.5,2817.5 2777.5,2820 2787.5,2830 R28.1
NetP1_3: P1.3 R30.1 | length 296
  Top Layer w10: P1.3 2735,2775 2745,2785 2765,2785 2777.5,2772.5 2777.5,2770 2787.5,2760 R30.1
NetPPS1_1: PPS1.1 R27.2 | length 93
  Top Layer w20: R27.2 2190,2327.5 2195,2322.5 2204.22,2322.5 2206.72,2320 PPS1.1
NetPPS2_1: PPS2.1 R33.1 | length 461.6
  Top Layer w20: R33.1 2425,2410 2470,2455 2470,2560 2580,2670 PPS2.1
NetPPS3_1: PPS3.1 R34.1 | length 337.3
  Top Layer w20: R34.1 2400,2480 2425,2505 2425,2575 2490,2640 PPS3.1
NetQ1_2: Q1.2 R52.1 | length 83.2
  Top Layer w20: R52.1 4505,3572.4 4510,3577.4 Q1.2
NetQ1_3: Q1.3 R53.1 | length 115.5
  Top Layer w20: R53.1 4675,3541.26 Q1.3
NetR20_1: R20.1 U3.5 | length 168.3
  Top Layer w20: U3.5 4228.28,3200 4240,3211.72 R20.1
NetR23_1: R23.1 R24.1 | length 75
  Top Layer w10: R24.1 R23.1
NetR23_2: R23.2 R26.1 U4.17 | length 517.7
  Top Layer w10: R23.2 R26.1 3320,4675 3360,4715 U4.17
NetR25_2: R25.2 U4.3 | length 236.4
  Top Layer w10: U4.3 3885,4695 3975,4605 4030,4605 R25.2
NetR31_1: R31.1 U4.19 | length 159.4
  Top Layer w10: R31.1 3625,4655 3645,4675 U4.19
NetR35_1: R35.1 U7.14 | length 123.2
  Top Layer w10: R35.1 2121.64,4246.64 2121.64,4271.64 2171.1,4321.1 2171.1,4346.8 U7.14
NetR36_1: R36.1 U7.1 | length 139.3
  Top Layer w10: U7.1 2230.35,4314.65 2260,4285 R36.1
NetR39_2: R39.2 U8.6 | length 153.8
  Top Layer w10: R39.2 1620,3915 1635,3930 U8.6
NetR40_2: R40.2 U8.5 | length 160
  Top Layer w10: R40.2 1591.64,3973.36 1611.64,3973.36 1635,3950 U8.5
NetR47_2: R47.2 U9.6 | length 144.4
  Top Layer w10: R47.2 3872.5,3920 3882.5,3930 3882.5,3932.5 3895,3945 U9.6
NetR48_2: R48.2 U9.5 | length 138.8
  Top Layer w10: R48.2 3872.5,3980 3887.5,3965 U9.5
OUT1+: C42.2 J2.2 U8.2 | length 429.3
  Top Layer w10: U8.2 1960,3910 1967.5,3902.5 1970,3902.5 1980,3892.5 C42.2
  Top Layer w40: C42.2 1980,3845 2020,3805 2174,3805 J2.2
OUT1-: C42.1 J2.1 U8.3 | length 538.4
  Top Layer w10: U8.3 1960,3930 1967.5,3937.5 1970,3937.5 1980,3947.5 C42.1
  Top Layer w40: C42.1 1980,3980 2015,4015 2135,4015 2175,3975 J2.1
OUT2+: C50.2 J3.2 U9.2 | length 366.7
  Top Layer w10: U9.2 4202.5,3925 4230,3897.5 C50.2
  Top Layer w40: C50.2 4230,3865 4290.9,3804.1 J3.2
OUT2-: C50.1 J3.1 U9.3 | length 516.2
  Top Layer w10: U9.3 4220,3945 C50.1
  Top Layer w40: C50.1 4230,4006.57 4253.43,4030 4361.57,4030 4385,4006.57 J3.1
OUT-5V: C11.2 C12.2 C13.2 D4.1 J2.3 J3.3 L1.1 P2.7 P3.1 P4.5 P4.6 P5.5 Q1.1 R3.1 R4.1 R5.1 R6.1 R21.2 | length 9567.7
  Top Layer w20: C13.2 4030.44,3115 R21.2 4095,3065 4295,2865 4555,2865 4562.44,2857.56 D4.1@4562.44,2852.56 ; D4.1@4564.41,2849.53 4580,2833.94 D4.1
  Top Layer w40: v1(1550.23,3684.77) 1845,3390 1975,3390 2030,3445 R5.1 ; R3.1 2081.9,3746.9 J2.3 2268.1,3746.9 2365,3650 2365,3500 ; R5.1@2040,3500 2365,3500 ; 4230,3405 R6.1 ; R4.1 4280,3745 J3.3 4386.39,3743.61 4421.27,3743.61 4440,3724.88 4440,3415 ; D4.1 4580,2826.06 4574.41,2820.47 4570.47,2820.47 4520,2770 4255,2770 3870,3155 ; Q1.1 4583.74,3423.43 4560.31,3400 3925,3400 3865,3340 3865,3160 3870,3155 ; L1.1 5035,2875 5095,2935 P4.6@5250,2935 ; P4.6 P4.5 5358.65,2943.65 5385.69,2943.65 5415,2972.96 5415,3920 5340,3995 P5.5 ; 2365,3500 2710,3155 3870,3155
  Bottom Layer w40: P2.7 1068.65,2958.65 1098.65,2958.65 1165,3025 1165,3746.9 ; P3.1 1106.9,3746.9 1165,3746.9 ; v1(1550.23,3684.77) 1488.1,3746.9 1165,3746.9
P0.0: P2.1 U1.39 | length 869.2
  Top Layer w10: P2.1 1155,3555 1260,3450 1260,3155 1432.2,2982.8 U1.39
P0.1: P2.2 U1.40 | length 768.6
  Top Layer w10: P2.2 1110,3455 1235,3330 1235,3150 1421.89,2963.11 U1.40
P0.2: P2.3 U1.41 | length 706.2
  Top Layer w10: P2.3 1125,3355 1205,3275 1205,3145 1330,3020 1330.36,3020 1345,3005.36 1345,3005 1406.58,2943.43 U1.41
P0.3: P2.4 U1.43 | length 666.6
  Top Layer w10: P2.4 1070,3250 1130,3250 1180,3200 1180,3094.42 1370.36,2904.06 U1.43
P0.4(T3): R4.2 R9.2 U1.44 | length 3659.7
  Top Layer w10: v1(1346.43,2890) 1352.06,2884.37 U1.44 ; v1(3185,3235) 3580,3235 3692,3347 3692,3552 3770,3630 R9.2
  Top Layer w20: R9.2 R4.2
  Bottom Layer w10: v1@1349.11,2887.32 1349.11,2902.58 1349.24,2902.71 1349.24,3169.24 1415,3235 3113.79,3235 3114.64,3235.86 3135.36,3235.86 3136.21,3235 v1(3185,3235)
P0.5: R5.2 R11.2 U1.45 | length 1628.9
  Top Layer w10: v1(1260,2871.25) 1260,2870 1255,2865 1455,2865 1455.32,2864.69 U1.45 ; v1(1830,3565) R11.2
  Top Layer w20: R5.2 R11.2
  Bottom Layer w10: v1(1260,2871.25) 1260,2874.11 1250,2884.11 1250,3340 1475,3565 v1(1830,3565)
P0.6(T4): R3.2 R8.2 U1.46 | length 1737.4
  Top Layer w10: v1(1220,2870) 1220,2860 1235,2845 U1.46 ; v1(1835,3625) 1965,3625 R8.2
  Top Layer w20: R8.2 R3.2
  Bottom Layer w10: v1(1220,2870) 1220,3360 1485,3625 v1(1835,3625)
P1.0（PWM1）: R40.1 U1.48 | length 1533.3
  Top Layer w10: v1(1290,3182.86) 1290,3825 1445,3980 R40.1 ; v1(1320,2810) 1323.79,2810 1328.79,2805 1493.31,2805 1493.94,2805.63 U1.48
  Bottom Layer w10: v1(1290,3182.86) 1290,2841 1320,2811 v1(1320,2810)
P1.1: P2.5 U1.3 | length 1068.1
  Top Layer w10: P2.5 1135,3155 1150,3140 1150,2850 1400,2600 1575,2600 1636.57,2661.57 U1.3
P1.2: P6.2 U1.4 | length 758.2
  Top Layer w10: P6.2 1230,2715 1365,2580 1585,2580 1656.26,2651.26 U1.4
P1.3: P7.1 U1.5 | length 4622.6
  Top Layer w10: U1.5 1675.94,2652.84 1685,2643.79 v1(1685,2640)
  Bottom Layer w10: v1(1685,2640) 1717,2608 1933,2608 2090,2765 3450,2765 3515,2700 3515,2595 3665,2445 3800,2445 3903,2342 4382,2342 4475,2435 4930,2435 5185,2690 5185,3150 5250,3215 P7.1
P2.0: key2.1 R49.2 U1.30 | length 2320.2
  Top Layer w10: v1(1690,3020) 1715.32,3045.32 U1.30
  Top Layer w20: v1(3645,2670) 3650,2675 R49.2@3650,2775
  Bottom Layer w10: v1(1690,3020) 1690,2920 1710,2900 3555,2900 3650,2805 v1@3650,2785
  other v1: 3650,2780
P2.1: D3.2 U1.32 | length 2840.1
  Top Layer w10: v1(1650,3020) 1675.94,3045.94 U1.32
  Bottom Layer w10: v1(1650,3020) 1650,2905 1680,2875 3534.14,2875 3609.14,2800 3615,2794.14 3615,2750 3660,2705 3890,2705 3910,2685 3910,2510 3952.01,2467.99 v1(3980,2467.99)
P2.2（PWM4）: R47.1 U1.33 | length 2672
  Top Layer w10: U1.33 1656.26,3236.26 1700,3280 v1(1700,3285) ; v1(3740.18,3918.28) 3740.18,3916.39 3743.16,3919.38 3809.38,3919.38 R47.1
  Bottom Layer w10: v1@1705,3278 1700,3283 v1(1700,3285) 2685,3285 2945,3545 3500,3545 3700,3745 3700,3880 3738.28,3918.28 v1(3740.18,3918.28)
P2.3: P7.2 U1.34 | length 4450.7
  Top Layer w10: v1(1605,3020) 1636.57,3051.57 U1.34
  Bottom Layer w10: v1(1605,3020) 1605,3065 1623,3083 3922,3083 4315,2690 5025,2690 5165,2830 5165,3220 5260,3315 P7.2
P2.4（PWM3）: R48.1 U1.35 | length 2745.3
  Top Layer w10: U1.35 1616.89,3271.89 1662.32,3317.32 1672.32,3317.32 v1(1675,3320) ; v1(3730,3975) 3733.79,3975 3738.79,3980 R48.1
  Bottom Layer w10: v1(1675,3320) 2655,3320 2920,3585 3480,3585 3672,3777 3672,3917 v1(3730,3975)
P2.5: P7.3 U1.36 | length 4588.6
  Top Layer w10: v1(1511.61,3132.72) 1509.14,3130.26 1509.14,3110.86 1523.06,3096.94 1597.2,3096.94 U1.36
  Bottom Layer w10: v1(1511.61,3132.72) 1534.33,3110 3940,3110 4330,2720 5005,2720 5145,2860 5145,3300 5260,3415 P7.3
P2.6（PWM2）: R39.1 U1.37 | length 1123.1
  Top Layer w10: U1.37 1482.83,3022.17 1380,3125 1380,3125.36 1365.36,3140 1365,3140 1340,3165 1340,3820 1435,3915 R39.1
P2.7: R6.2 R12.2 U1.38 | length 3383.7
  Top Layer w10: v1(1375,3085) 1457.52,3002.48 U1.38 ; v1(3125,3210.86) 3125.86,3210 3605,3210 3730,3335 3730,3530 3765,3565 R12.2
  Top Layer w20: R6.2 R12.2
  Bottom Layer w10: v1(1375,3085) 1375,3130 1455,3210 3124.14,3210 v1(3125,3210.86)
P3.6: P6.1 U1.27 | length 976.1
  Top Layer w10: v1(1290,2775) 1570,2775 1590,2795 1590,2902.5 1667.5,2980 1752.6,2980 1774.37,3001.77 U1.27
  Bottom Layer w10: P6.1 1105,2775 v1(1290,2775)
P3.7（INT3）干簧管: P3.2 U1.28 | length 1225.1
  Top Layer w10: v1(1420,3805) 1420.86,3805.86 1454.14,3805.86 1490,3770 1490,3620 1755,3355 1755,3125.74 1754.68,3125.43 U1.28
  Bottom Layer w10: P3.2 v1(1420,3805)
P4.3: R52.2 U1.42 | length 3756.4
  Top Layer w10: v1(1319.38,2995.17) 1320,2994.54 1320.46,2995 1391.72,2923.74 U1.42
  Bottom Layer w10: v1(1319.38,2995.17) 1320,2995.79 1320,3205 1375,3260 2710,3260 2960,3510 v1(4505,3510)
P5.2: key4.1 R51.2 U1.1 | length 2137.1
  Top Layer w10: v1(1535,2635) 1537.68,2637.68 1537.68,2657.68 1555,2675 1580,2675 1597.2,2692.2 U1.1
  Top Layer w20: key4.1 v1(3280,2675) 3280,2684.84 3295,2699.84 R51.2@3295,2789.79
  Bottom Layer w10: v1(1535,2635) 1535,2582.86 1547.86,2570 1985,2570 2120,2705 3165,2705 3195,2675 v1(3280,2675)
P5.3: key3.1 R50.2 U1.2 | length 2250.3
  Top Layer w10: v1(1570.18,2634.82) 1570.18,2635.18 1616.89,2681.89 U1.2
  Top Layer w20: v1(3465,2670) R50.2
  Bottom Layer w10: v1(1570.18,2634.82) 1570.18,2604.82 1585,2590 1965,2590 2110,2735 3400,2735 v1(3465,2670)
POWER-MCU: C3.2 C4.2 C5.2 C31.2 J4.1 J5.1 OLED1.2 P4.3 P4.4 R1.1 R2.1 R7.1 R10.1 R17.1 R27.1 R33.2 R34.2 R49.1 R50.1 R51.1 R54.2 reset.2 U1.15 U5.5 | length 11436.9
  Top Layer w10: 1750,2926.29 1750,2880 1785,2845 U1.15
  Top Layer w20: v1(1626.25,2863.75) 1625,2865 1699.94,2939.94 v1(1750.5,2939.94) ; v1(2190,2390) 2190,2392.5 2255.78,2392.5 2267.5,2404.22 2267.5,2405 2272.5,2410 R33.2 R34.2 ; R51.1 R50.1 3645,2845 R49.1 3655,2845 3655,2850 3690,2885 3935,2885 3980,2840 R54.2 3985,2685 R2.1 R1.1 4260,2685 4300,2645 OLED1.2 ; reset.2 3820,2379.84 3839.53,2399.37 3849.37,2399.37 3880,2430 C5.2 ; U5.5 4842.4,2622.4 C31.2
  Top Layer w30: R17.1 2220,2890 2265,2935 v1(2320,2935) ; v1(2350,3035) 2350,3255 v1(2445,3350) ; v1(2535,3440) 2575,3480 3220,3480 ; R10.1 3222.5,3482.5 3220,3480 ; R7.1 3435,3480 ; J5.1 J4.1 3580,3555 3505,3480 3435,3480 ; 3220,3480 3435,3480
  Top Layer w40: reset.2 3820,2360.16 3829.53,2350.63 3839.37,2350.63 3870,2320 4295,2320 ; OLED1.2 4300,2325 4295,2320 ; v1(4910,2590) 4910,2430 4800,2320 4295,2320 ; 4915,2610 4916.57,2611.57 5011.57,2611.57 5055,2655 5055,2740 5155,2840 P4.3
  Bottom Layer w20: v1(1626.25,2863.75) 1626.25,2801.25 1575,2750 1515,2750 1475,2710 1475,2575 1520,2530 2015,2530 2155,2390 v1(2190,2390)
  Bottom Layer w30: v1(2320,2935) 2350,2965 v1(2350,3035) ; v1(2445,3350) v1(2535,3440)
  Bottom Layer w40: v1(1750.5,2939.94) C4.2 1750.5,3010.1 1778.4,3038 1831.6,3038 1834.6,3035 v1(2350,3035) ; v1@2355,3035 3840,3035 4250,2625 v1(4910,2625)
  other v1: 4950,2590 4950,2625
REST: C5.1 R16.2 reset.1 U1.14 | length 2322.7
  Top Layer w10: U1.14 1970.32,2825.32 v1@1996.55,2851.55 ; v1@1996.21,2850 v1(2000,2850) ; v1(3820,2670) reset.1@3825,2675
  Top Layer w20: reset.1@3825,2675 R16.2
  Bottom Layer w10: v1(2000,2850) 3509.54,2850 3590,2769.54 3590,2635 3625,2600 3775,2600 3820,2645 v1(3820,2670)
RX: P5.3 U1.25 | length 4785.4
  Top Layer w10: U1.25 1813.74,3168.28 1822.46,3177 1883,3177 v1(1912.5,3147.5)
  Bottom Layer w10: v1(1912.5,3147.5) 1915,3145 3940,3145 4340,2745 4995,2745 5125,2875 5125,3390 5225,3490 5325,3490 5385,3550 5385,3715 5345,3755 5300,3755 P5.3@5260,3795
RXD: R32.2 U1.20 | length 684.5
  Top Layer w10: U1.20 2073.43,2943.43 2115,2985 2510,2985 2527.5,3002.5 2527.5,3005 2537.5,3015 R32.2
RXD_1: PPS3.2 R32.1 U6.7 | length 868.6
  Top Layer w10: R32.1 2605,3010 2750,3010 2802,2958 3088,2958 3107,2977 3107,3003 3090,3020 U6.7
  Top Layer w20: PPS3.2 2490,2804.57 2505,2819.57 2507.56,2819.57 2600,2912.01 R32.1
SA0/SD0: J5.5 R10.2 R14.2 U1.22 | length 2542.2
  Top Layer w10: U1.22 1973.25,2982.8 2090,3099.54 2090,3255 2220,3385 v1(2315,3385) ; v1(3137.84,4063.41) 3141.59,4063.41 3180,4025 J5.5 3230,3875 3230,3650 3222.5,3642.5 3220,3642.5 R10.2@3213.75,3636.25 ; R10.2@3215,3635 R10.2@3222.5,3635 ; R10.2 3230,3640 3280,3640 R14.2@3280,3645
  Bottom Layer w10: v1(2315,3385) 2375,3385 2510,3520 2510,3865 2710,4065 3136.25,4065 v1(3137.84,4063.41)
SCL: OLED1.3 R1.2 U1.8 | length 3041.8
  Top Layer w10: U1.8 v1(1735,2805)
  Top Layer w20: OLED1.3 R1.2
  Bottom Layer w10: v1(1735,2805) 1752,2822 1798,2822 1850,2770 2060,2770 2085,2795 3485,2795 3540,2740 3540,2625 3700,2465 3840,2465 3945,2360 4120,2360 4158,2398 4158,2463 OLED1.3
SCL-1: J5.3 R7.2 R13.2 U1.21 | length 2646.9
  Top Layer w10: U1.21 1983.11,2963.11 2110,3090 2110,3240 2220,3350 v1(2340,3350) ; R13.2 R13.2@3379.14,3654.14 ; R13.2@3380,3645 3384.54,3640.46 3430,3640.46 3430,3875 J5.3
  Bottom Layer w10: v1(2340,3350) 2385,3350 2540,3505 2540,3840 2715,4015 3335,4015 3380,3970 J5.3
SDA: OLED1.4 R2.2 U1.6 | length 3062.5
  Top Layer w10: v1(1695,2805) 1695.63,2804.37 U1.6
  Top Layer w20: OLED1.4 R2.2
  Bottom Layer w10: v1(1695,2805) 1697.68,2807.68 1697.68,2817.68 1720,2840 1810,2840 1855,2795 2045,2795 2065.47,2815.47 3492.56,2815.47 3558,2750.03 3558,2632.46 3707.46,2483 3872,2483 3977,2378 4112.54,2378 4140,2405.46 4140,2465 OLED1.4
SDA/SDI: J5.4 U1.23 | length 2287.5
  Top Layer w10: U1.23 1967.48,3002.48 2072,3107 2072,3272 2215,3415 v1(2295,3415) ; v1(3225,4095) 3280,4040 J5.4
  Bottom Layer w10: v1(2295,3415) 2355,3415 2480,3540 2480,3890 2690,4100 v1@3225,4100
T_VIN: J6.1 J7.1 | length 594.1
  Top Layer w80: J6.1 4792.5,4567.5 4884.78,4475.22 5026.43,4475.22 J7.1
TX: P5.2 U1.26 | length 4734
  Top Layer w10: U1.26 1794.06,3174.06 1815,3195 1934.46,3195 1947.14,3182.32 v1(1947.32,3182.32)
  Bottom Layer w10: v1(1947.32,3182.32) 1949.64,3180 3945,3180 4355,2770 4985,2770 5105,2890 5105,3400 5220,3515 5310,3515 5360,3565 5360,3714.54 5337.54,3737 5302,3737 P5.2@5260,3695
TXD: D1.1 U1.19 | length 685
  Top Layer w10: U1.19 2083.74,2923.74 2125,2965 2504.61,2965 2510.47,2959.14 2510.47,2950.59 2531.06,2930 D1.1
TXD_1: D1.2 PPS2.2 U6.6 | length 775.8
  Top Layer w10: D1.2 2675,2970 2690,2985 2745,2985 2790,2940 3105,2940 3125,2960 3125,3005 3140,3020 U6.6
  Top Layer w20: PPS2.2 2580,2806.93 2595,2821.93 2597.56,2821.93 2661.76,2886.13 2661.76,2916.76 D1.2
"USB D+": R30.2 U6.1 | length 349.5
  Top Layer w10: R30.2 2860,2770 2862.99,2770 2877.43,2784.44 2880.55,2784.44 2881.11,2785 2940,2785 2978,2823 2978,2868 2994.77,2884.77 3039.77,2884.77 3055,2869.54 3055,2855 3047.5,2847.5 3047.5,2823.09 U6.1
"USB D-": R28.2 U6.2 | length 382.8
  Top Layer w10: R28.2 2860,2820 2862.99,2820 2879.99,2803 2932.54,2803 2960,2830.46 2960,2875.46 2987.32,2902.77 2987.77,2902.77 2990,2905 3045,2905 3075,2875 3075,2850.59 3090,2835.59 U6.2
V_SNS: C44.1 R43.1 R45.2 U7.7 | length 467.9
  Top Layer w10: U7.7 2230.47,4560.47 2270,4600 2270,4720 2300,4750 2300,4785 R43.1 2365,4860 C44.1
VCC-CH340: C27.1 C34.2 F1.2 S1.2 U6.5 | length 957
  Top Layer w20: S1.2 3117.09,2492.09 3157.09,2492.09 3200,2535 3200,2720 3235,2755 3235,2940 3264.94,2969.94 C34.2 ; U6.5@3190,3039.5 C34.2@3263.94,3039.5
  Bottom Layer w40: C27.1 2980,2595 F1.2 S1.2
Vref+: C7.1 R18.2 U1.12 U2.1 U2.2 | length 504.8
  Top Layer w10: U1.12 1813.74,2732.52 U2.2@2142.6,2732.52 ; U2.2 2148.86,2735 2211.14,2735 U2.1 ; U2.1@2217.4,2732.52 2302.52,2732.52 R18.2
XCL: J4.6
XDA: J4.5
XTAL0: C1.1 U1.9 Y1.2 | length 375.7
  Top Layer w10: Y1.2 1686.26,2417.87 1720.63,2452.24 1727.24,2452.24 1755,2480 1755,2540 C1.1 1754.68,2589.68 U1.9
XTAL1: C2.1 U1.10 Y1.1 | length 378.5
  Top Layer w10: U1.10 1774.37,2590.63 C2.1 1773,2538 1773,2480.74 1801.5,2452.24 1809.37,2452.24 1843.74,2417.87 Y1.1
pads on no net: J6.3 P1.0 P1.4 P3.3 P5.1 P5.6 S1.1 U1.7 U1.16 U1.18 U1.29 U1.31 U1.47 U4.13 U6.4 U8.9 U9.9
copper on no net: | length 1.9
  Top Layer w40: 5260,4090 5261.35,4091.35
  other v2: 2648.39,2408.27 2821.61,2408.27

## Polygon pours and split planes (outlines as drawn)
GND on Top Layer "Top Layer-No Net" (solid, remove dead copper, pour order 4): 755,5225 5930,5225 5940,5215 5925,5200 5925,1995 740,1995 720,2015 745,2040 745,5220
no net on Top Layer "Top Layer-No Net" (solid, remove dead copper, pour order 2): 1685,5420
GND on Bottom Layer "Top Layer-No Net" (solid, remove dead copper, pour order 3): 745,5220 5920,5220 5920,1990 5915,1985 5870,2030 750,2030

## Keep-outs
Keep-Out Layer:
  circle w10: c3520,3355 r59.06
  circle w10: c2940,3355 r59.06
  lines w10: 965,2415 965,4870 cw(c1137.5,4882.5) 1125,5055 5265,5055 cw(c5277.5,4882.5) 5450,4895 5450,2445 cw(c5277.5,2432.5) 5290,2260 1135,2260 ; 965,2420 ccw(c1137.5,2432.5) 1150,2260

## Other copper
Top Layer:
  rectangle net GND: 1130,4580 1465,4680
  rectangle net DRV-6V: 1135,4410 1575,4520
  rectangle net GND: 2185,4205 2215,4950
  rectangle net GND: 3685,4810 3782.63,4890
  rectangle net GND: 3730,4505 3785,5005
  rectangle net BOOST_IN: 3945,4810 4665,4885
  rectangle net BOOST_IN: 4565,4380 4665,4955
  rectangle net DRV-6V: 4075,3880 4124.53,3910
  rectangle net DRV-6V: 4055,3670 4124.53,3890
  rectangle net DRV-6V: 4075,3790 4105,3910
  rectangle net DRV-6V: 1817.4,3865 1860,3891
  rectangle net DRV-6V: 1785,3665 1860,3875
  rectangle net DRV-6V: 1805,3665 1830,3890
  rectangle net NetC6_1: 4340,3150 4380,3210
  rectangle net 12V-VCC: 4285,3225 4650,3320
  rectangle net OUT-5V: 4550,2835 4855,2915
  rectangle net OUT-5V: 4545,2795 4620,3075
  rectangle net POWER-MCU: 4750.43,2575 4970,2646.02
  rectangle net GND: 4560,2455.01 4679.57,2580
  rectangle net GND: 2785,2590 2860,2680
  rectangle net GND: 2785,2590 2810,2680
  rectangle net 5V-VCC: 4555,2615 4605,2725
  rectangle net 5V-VCC: 4525,2610 4680,2635
  rectangle net NetF1_1: 2610,2580 2680,2655
  pour cut-out: 4665,3247.5 4667.5,3250 5010,3250 5010,2820 4660,2820
  pour cut-out: 1485,4670 1920,4670 1920,4295 1485,4295
  pour cut-out: 4205,4660 4680,4660 4680,4270 4205,4270
  region net NetC35_1: 2140,4425 2140,4395 1945.44,4395 1910.44,4360 1845,4360 1815,4390 1815,4575 1820,4580 1900,4580 1920,4560 1920,4520 2015,4425
  region net GND: 2210,4405 2355,4405 2430,4330 2630,4330 2655,4305 2655,4255 2635,4235 2440,4235 2295,4380 2210,4380
  region net GND: 3713,4810 3655,4810 3575,4890 2760,4890 2725,4925 2725,5030 2740,5045 4485,5045 4500,5030 4500,4980 4485,4965 4050,4965 3815,4965 3759.38,4909.38
  region net GND: 3280,4635 3250,4635 3240,4625 3240,4510 3290,4460 3980,4460 3990,4470 3990,4515 3975,4530 3685,4530 3340,4530 3285,4585 3285,4635
  region net 12V-VCC: 3715,4780 3635,4780 3585,4830 2940,4830 2860,4750 2765,4655 2350,4655 2265,4570 2265,4415 2745,4415 3015,4685 3015,4735 3590,4735 3715,4735
  region net NetC10_2: 3820,4780 3940,4780 3988.81,4731.19 4248.81,4731.19 4335,4645 4335,4320 4325,4310 4280,4310 4230,4360 4230,4500 4095,4635 3985,4635 3910,4710 3820,4710
  region net BOOST_IN: 3820,4810 3820,4845 3900,4925 4655,4925 4665,4915 4665,4825 4650,4810
Bottom Layer:
  rectangle net POWER-MCU: 4890,2575 4970,2645
  rectangle net NetC6_1: 4340,3150 4895,3220
  rectangle net GND: 2785,2590 2920,2680
  rectangle net NetF1_1: 2610,2580 2680,2655
  pour cut-out: 4665,3247.5 5007.5,3247.5 5010,3245 5010,2820 4660,2820 4665,2825
  pour cut-out: 4205,4660 4680,4660 4680,4270 4675,4275 4205,4275
  pour cut-out: 1485,4670 1925,4670 1925,4295 1480,4295

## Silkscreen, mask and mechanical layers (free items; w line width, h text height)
Top Overlay:
  text "成都信息工程大学" at 2855,4311.47 h100
  text "BOOM BOOM BOOM!" at 2875,4193.24 h100
  text "6.19" at 3120,4087.87 h100
  text "GND" at 1145,3998.93 h36
  text "+5V" at 5345,3979.07 h36
  text "GND" at 5345,3878.93 h36
  text "P3.7" at 1140,3789.23 h36
  text "RXD" at 5340,3783.5 h36
  text "+5" at 1135,3683.93 h36
  text "TXD" at 5335,3683.5 h36
  text "P0.0" at 1135,3539.23 h36
  text "P0.1" at 1135,3444.23 h36
  text "P2.5" at 5340,3409.23 h36
  text "P0.2" at 1135,3334.23 h36
  text "P2.3" at 5340,3309.23 h36
  text "P0.3" at 1135,3244.23 h36
  text "P1.3" at 5340,3204.23 h36
  text "P1.1" at 1142.5,3146.73 h36
  text "GND" at 1136.91,3035.57 h36
  text "+12" at 5135,3023.5 h36
  text "+5" at 1145,2943.93 h36
  text "+5" at 5135,2928.93 h36
  text "+3.3" at 5130,2829.23 h36
  text "P3.6" at 1135,2804.23 h36
  text "GND" at 5140,2728.93 h36
  text "P1.2" at 1135,2704.23 h36
Mechanical 1:
  lines w10: 965,2420 965,4890 cw(c1140,4880) 1150,5055 5282.5,5055 ; 965,2445 ccw(c1140,2435) 1130,2260 5285,2260 ; 3000,3360 ccw(c2941.06,3356.32) 3000.12,3356.32 ; 3459.88,3356.32 ccw(c3518.94,3356.32) 3460,3360 ; 5285,5055 cw(c5275,4880) 5450,4870 5450,2425 ; 5450,2425 cw(c5275,2435) 5265,2260 ccw(c5275,2435) 5450,2425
